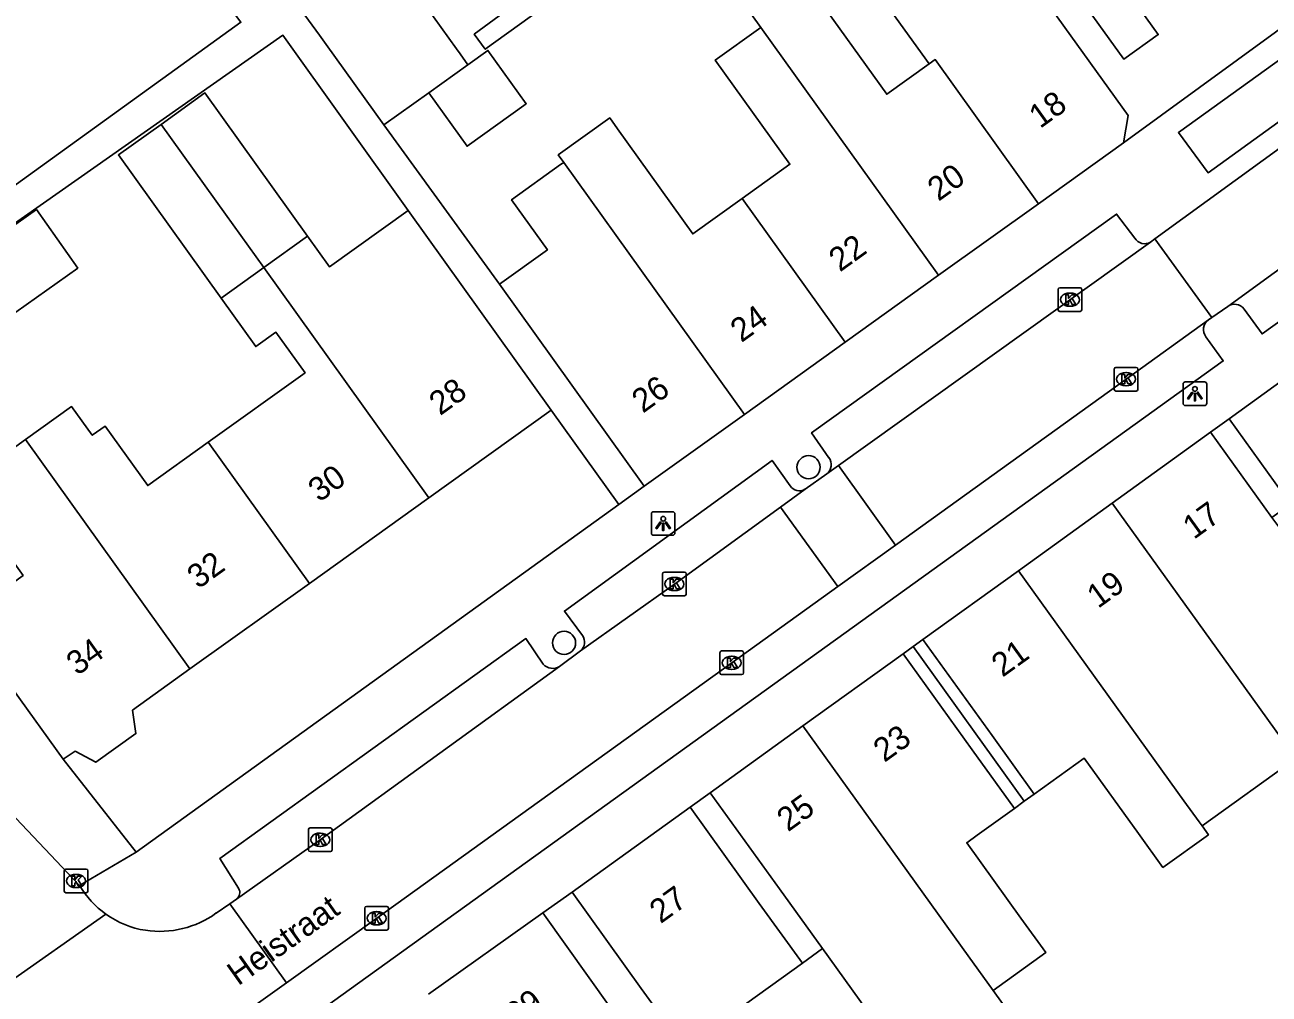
# Model space of a CAD drawing. Extents: x 161882 to 162509, y 381687 to 382379.
# Drawn here: x 162223.5 to 162276, y 381897.9 to 381938.8 of the extents above; entities that cross this region are included whole.
import ezdxf

# ---------------------------------------------------------------- set-up
doc = ezdxf.new("R2010")
doc.units = 0
for name, color, linetype in [('IMGEO_Boom', 7, 'Continuous'), ('IMGEO_Kolk', 7, 'Continuous'), ('IMGEO_Lichtpunt', 7, 'Continuous'), ('IMGEO_Openbare_ruimte_label', 7, 'Continuous'), ('IMGEO_Pand', 7, 'Continuous'), ('IMGEO_Pand_nummerreeks', 7, 'Continuous'), ('IMGEO_Pand_overbouw', 7, 'Continuous'), ('IMGEO_Rijbaan_lokaal_open', 7, 'Continuous'), ('IMGEO_Voetpad_open', 7, 'Continuous')]:
    doc.layers.add(name, color=color, linetype=linetype)

msp = doc.modelspace()

# ---------------------------------------------------------------- linework, layer by layer
at = {"layer": 'IMGEO_Boom'}
for centre in [(162256.59, 381920.171), (162246.271, 381912.756)]:
    msp.add_circle(centre, 0.489, dxfattribs=at)
at = {"layer": 'IMGEO_Kolk'}
for p, q in [((162267.12, 381926.817), (162267.12, 381927.669)), ((162267.195, 381927.743), (162268.047, 381927.743)), ((162267.608, 381927.523), (162267.633, 381927.523)), ((162268.121, 381927.669), (162268.121, 381926.817)), ((162267.631, 381926.963), (162267.606, 381926.963)), ((162268.047, 381926.743), (162267.195, 381926.743)), ((162269.563, 381924.384), (162270.415, 381924.384)), ((162269.488, 381923.458), (162269.488, 381924.31)), ((162269.976, 381924.164), (162270.001, 381924.164)), ((162270.489, 381924.31), (162270.489, 381923.458)), ((162270.415, 381923.384), (162269.563, 381923.384)), ((162269.999, 381923.604), (162269.974, 381923.604)), ((162250.428, 381914.817), (162250.428, 381915.669)), ((162250.503, 381915.743), (162251.355, 381915.743)), ((162250.916, 381915.523), (162250.941, 381915.523)), ((162251.429, 381915.669), (162251.429, 381914.817)), ((162250.939, 381914.963), (162250.914, 381914.963)), ((162251.355, 381914.743), (162250.503, 381914.743)), ((162252.846, 381911.491), (162252.846, 381912.343)), ((162252.921, 381912.417), (162253.773, 381912.417)), ((162253.847, 381912.343), (162253.847, 381911.491)), ((162253.334, 381912.197), (162253.359, 381912.197)), ((162253.773, 381911.417), (162252.921, 381911.417)), ((162253.357, 381911.637), (162253.332, 381911.637)), ((162235.558, 381904.95), (162236.41, 381904.95)), ((162235.483, 381904.024), (162235.483, 381904.876)), ((162235.971, 381904.73), (162235.996, 381904.73)), ((162236.484, 381904.876), (162236.484, 381904.024)), ((162236.41, 381903.95), (162235.558, 381903.95)), ((162235.994, 381904.17), (162235.969, 381904.17)), ((162225.176, 381902.283), (162225.176, 381903.135)), ((162225.251, 381903.209), (162226.103, 381903.209)), ((162225.664, 381902.989), (162225.689, 381902.989)), ((162226.177, 381903.135), (162226.177, 381902.283)), ((162225.687, 381902.429), (162225.662, 381902.429)), ((162226.103, 381902.209), (162225.251, 381902.209)), ((162237.861, 381900.708), (162237.861, 381901.56)), ((162237.936, 381901.634), (162238.788, 381901.634)), ((162238.349, 381901.414), (162238.374, 381901.414)), ((162238.862, 381901.56), (162238.862, 381900.708)), ((162238.372, 381900.854), (162238.347, 381900.854)), ((162238.788, 381900.634), (162237.936, 381900.634))]:
    msp.add_line(p, q, dxfattribs=at)
for points in [[(162267.12, 381926.817), (162267.12, 381927.669)], [(162267.195, 381927.743), (162268.047, 381927.743)], [(162268.121, 381927.669), (162268.121, 381926.817)], [(162267.441, 381927.443), (162267.564, 381927.443), (162267.564, 381927.292), (162267.694, 381927.443), (162267.858, 381927.443), (162267.712, 381927.292), (162267.865, 381927.043), (162267.713, 381927.043), (162267.628, 381927.207), (162267.564, 381927.14), (162267.564, 381927.043), (162267.441, 381927.043), (162267.441, 381927.443)], [(162268.047, 381926.743), (162267.195, 381926.743)], [(162269.563, 381924.384), (162270.415, 381924.384)], [(162269.488, 381923.458), (162269.488, 381924.31)], [(162269.809, 381924.084), (162269.932, 381924.084), (162269.932, 381923.933), (162270.062, 381924.084), (162270.226, 381924.084), (162270.08, 381923.933), (162270.233, 381923.684), (162270.081, 381923.684), (162269.996, 381923.848), (162269.932, 381923.781), (162269.932, 381923.684), (162269.809, 381923.684), (162269.809, 381924.084)], [(162270.489, 381924.31), (162270.489, 381923.458)], [(162270.415, 381923.384), (162269.563, 381923.384)], [(162250.428, 381914.817), (162250.428, 381915.669)], [(162250.503, 381915.743), (162251.355, 381915.743)], [(162250.749, 381915.443), (162250.872, 381915.443), (162250.872, 381915.292), (162251.002, 381915.443), (162251.166, 381915.443), (162251.02, 381915.292), (162251.173, 381915.043), (162251.021, 381915.043), (162250.936, 381915.207), (162250.872, 381915.14), (162250.872, 381915.043), (162250.749, 381915.043), (162250.749, 381915.443)], [(162251.429, 381915.669), (162251.429, 381914.817)], [(162251.355, 381914.743), (162250.503, 381914.743)], [(162252.846, 381911.491), (162252.846, 381912.343)], [(162252.921, 381912.417), (162253.773, 381912.417)], [(162253.847, 381912.343), (162253.847, 381911.491)], [(162253.167, 381912.117), (162253.29, 381912.117), (162253.29, 381911.966), (162253.42, 381912.117), (162253.584, 381912.117), (162253.438, 381911.966), (162253.591, 381911.717), (162253.439, 381911.717), (162253.354, 381911.881), (162253.29, 381911.814), (162253.29, 381911.717), (162253.167, 381911.717), (162253.167, 381912.117)], [(162253.773, 381911.417), (162252.921, 381911.417)], [(162235.558, 381904.95), (162236.41, 381904.95)], [(162235.483, 381904.024), (162235.483, 381904.876)], [(162235.804, 381904.65), (162235.927, 381904.65), (162235.927, 381904.499), (162236.057, 381904.65), (162236.221, 381904.65), (162236.075, 381904.499), (162236.228, 381904.25), (162236.076, 381904.25), (162235.991, 381904.414), (162235.927, 381904.347), (162235.927, 381904.25), (162235.804, 381904.25), (162235.804, 381904.65)], [(162236.484, 381904.876), (162236.484, 381904.024)], [(162236.41, 381903.95), (162235.558, 381903.95)], [(162225.176, 381902.283), (162225.176, 381903.135)], [(162225.251, 381903.209), (162226.103, 381903.209)], [(162225.497, 381902.909), (162225.62, 381902.909), (162225.62, 381902.758), (162225.75, 381902.909), (162225.914, 381902.909), (162225.768, 381902.758), (162225.921, 381902.509), (162225.769, 381902.509), (162225.684, 381902.673), (162225.62, 381902.606), (162225.62, 381902.509), (162225.497, 381902.509), (162225.497, 381902.909)], [(162226.177, 381903.135), (162226.177, 381902.283)], [(162226.103, 381902.209), (162225.251, 381902.209)], [(162237.861, 381900.708), (162237.861, 381901.56)], [(162237.936, 381901.634), (162238.788, 381901.634)], [(162238.182, 381901.334), (162238.305, 381901.334), (162238.305, 381901.183), (162238.435, 381901.334), (162238.599, 381901.334), (162238.453, 381901.183), (162238.606, 381900.934), (162238.454, 381900.934), (162238.369, 381901.098), (162238.305, 381901.031), (162238.305, 381900.934), (162238.182, 381900.934), (162238.182, 381901.334)], [(162238.862, 381901.56), (162238.862, 381900.708)], [(162238.788, 381900.634), (162237.936, 381900.634)]]:
    msp.add_lwpolyline(points, dxfattribs=at)
for centre, start, end in [((162267.197, 381927.667), 91.552, 178.448), ((162267.197, 381927.667), 91.552, 178.448), ((162268.045, 381927.667), 1.552, 88.448), ((162268.045, 381927.667), 1.552, 88.448), ((162267.197, 381926.819), 181.552, 268.448), ((162267.197, 381926.819), 181.552, 268.448), ((162268.045, 381926.819), 271.552, 358.448), ((162268.045, 381926.819), 271.552, 358.448), ((162269.565, 381924.308), 91.552, 178.448), ((162269.565, 381924.308), 91.552, 178.448), ((162270.413, 381924.308), 1.552, 88.448), ((162270.413, 381924.308), 1.552, 88.448), ((162269.565, 381923.46), 181.552, 268.448), ((162269.565, 381923.46), 181.552, 268.448), ((162270.413, 381923.46), 271.552, 358.448), ((162270.413, 381923.46), 271.552, 358.448), ((162250.505, 381915.667), 91.552, 178.448), ((162250.505, 381915.667), 91.552, 178.448), ((162251.353, 381915.667), 1.552, 88.448), ((162251.353, 381915.667), 1.552, 88.448), ((162250.505, 381914.819), 181.552, 268.448), ((162250.505, 381914.819), 181.552, 268.448), ((162251.353, 381914.819), 271.552, 358.448), ((162251.353, 381914.819), 271.552, 358.448), ((162252.923, 381912.341), 91.552, 178.448), ((162252.923, 381912.341), 91.552, 178.448), ((162253.771, 381912.341), 1.552, 88.448), ((162253.771, 381912.341), 1.552, 88.448), ((162252.923, 381911.493), 181.552, 268.448), ((162252.923, 381911.493), 181.552, 268.448), ((162253.771, 381911.493), 271.552, 358.448), ((162253.771, 381911.493), 271.552, 358.448), ((162235.56, 381904.874), 91.552, 178.448), ((162235.56, 381904.874), 91.552, 178.448), ((162236.408, 381904.874), 1.552, 88.448), ((162236.408, 381904.874), 1.552, 88.448), ((162235.56, 381904.026), 181.552, 268.448), ((162235.56, 381904.026), 181.552, 268.448), ((162236.408, 381904.026), 271.552, 358.448), ((162236.408, 381904.026), 271.552, 358.448), ((162225.253, 381903.133), 91.552, 178.448), ((162225.253, 381903.133), 91.552, 178.448), ((162226.101, 381903.133), 1.552, 88.448), ((162226.101, 381903.133), 1.552, 88.448), ((162225.253, 381902.285), 181.552, 268.448), ((162225.253, 381902.285), 181.552, 268.448), ((162226.101, 381902.285), 271.552, 358.448), ((162226.101, 381902.285), 271.552, 358.448), ((162237.938, 381901.558), 91.552, 178.448), ((162237.938, 381901.558), 91.552, 178.448), ((162238.786, 381901.558), 1.552, 88.448), ((162238.786, 381901.558), 1.552, 88.448), ((162237.938, 381900.71), 181.552, 268.448), ((162237.938, 381900.71), 181.552, 268.448), ((162238.786, 381900.71), 271.552, 358.448), ((162238.786, 381900.71), 271.552, 358.448)]:
    msp.add_arc(centre, 0.0765, start, end, dxfattribs=at)
for centre, major_axis, ratio, start_param, end_param in [((162267.607, 381927.243), (-0.387, 0.002), 0.722429, 4.712389, 7.853982), ((162267.632, 381927.243), (-0.39, 0.002), 0.717154, 1.570796, 4.712389), ((162269.975, 381923.884), (-0.387, 0.002), 0.722429, 4.712389, 7.853982), ((162270, 381923.884), (-0.39, 0.002), 0.717154, 1.570796, 4.712389), ((162250.915, 381915.243), (-0.387, 0.002), 0.722429, 4.712389, 7.853982), ((162250.94, 381915.243), (-0.39, 0.002), 0.717154, 1.570796, 4.712389), ((162253.333, 381911.917), (-0.387, 0.002), 0.722429, 4.712389, 7.853982), ((162253.358, 381911.917), (-0.39, 0.002), 0.717154, 1.570796, 4.712389), ((162235.97, 381904.45), (-0.387, 0.002), 0.722429, 4.712389, 7.853982), ((162235.995, 381904.45), (-0.39, 0.002), 0.717154, 1.570796, 4.712389), ((162225.663, 381902.709), (-0.387, 0.002), 0.722429, 4.712389, 7.853982), ((162225.688, 381902.709), (-0.39, 0.002), 0.717154, 1.570796, 4.712389), ((162238.348, 381901.134), (-0.387, 0.002), 0.722429, 4.712389, 7.853982), ((162238.373, 381901.134), (-0.39, 0.002), 0.717154, 1.570796, 4.712389)]:
    msp.add_ellipse(centre, major_axis=major_axis, ratio=ratio, start_param=start_param, end_param=end_param, dxfattribs=at)
at = {"layer": 'IMGEO_Lichtpunt'}
for p, q in [((162272.395, 381923.676), (162272.395, 381922.869)), ((162272.395, 381923.676), (162272.395, 381922.869)), ((162273.297, 381923.771), (162272.489, 381923.771)), ((162273.297, 381923.771), (162272.489, 381923.771)), ((162273.391, 381922.869), (162273.391, 381923.676)), ((162273.391, 381922.869), (162273.391, 381923.676)), ((162272.489, 381922.775), (162273.297, 381922.775)), ((162272.489, 381922.775), (162273.297, 381922.775)), ((162249.955, 381918.2), (162249.955, 381917.393)), ((162249.955, 381918.2), (162249.955, 381917.393)), ((162250.857, 381918.295), (162250.049, 381918.295)), ((162250.857, 381918.295), (162250.049, 381918.295)), ((162250.951, 381917.393), (162250.951, 381918.2)), ((162250.951, 381917.393), (162250.951, 381918.2)), ((162250.049, 381917.299), (162250.857, 381917.299)), ((162250.049, 381917.299), (162250.857, 381917.299))]:
    msp.add_line(p, q, dxfattribs=at)
for points in [[(162272.769, 381923.34), (162272.808, 381923.312), (162272.62, 381923.05), (162272.582, 381923.077), (162272.769, 381923.34)], [(162272.871, 381923.292), (162272.918, 381923.292), (162272.918, 381922.97), (162272.871, 381922.97), (162272.871, 381923.292)], [(162272.981, 381923.312), (162273.019, 381923.339), (162273.206, 381923.077), (162273.167, 381923.049), (162272.981, 381923.312)], [(162250.329, 381917.864), (162250.368, 381917.836), (162250.18, 381917.574), (162250.142, 381917.601), (162250.329, 381917.864)], [(162250.431, 381917.816), (162250.478, 381917.816), (162250.478, 381917.494), (162250.431, 381917.494), (162250.431, 381917.816)], [(162250.541, 381917.836), (162250.579, 381917.863), (162250.766, 381917.601), (162250.727, 381917.573), (162250.541, 381917.836)]]:
    msp.add_lwpolyline(points, dxfattribs=at)
for centre in [(162272.894, 381923.474), (162250.454, 381917.998)]:
    msp.add_circle(centre, 0.0994, dxfattribs=at)
for centre, start, end in [((162272.489, 381923.676), 90, 180), ((162272.489, 381923.676), 90, 180), ((162273.297, 381923.676), 0, 90), ((162273.297, 381923.676), 0, 90), ((162272.489, 381922.869), 180, 270), ((162272.489, 381922.869), 180, 270), ((162273.297, 381922.869), 270, 0), ((162273.297, 381922.869), 270, 360), ((162250.049, 381918.2), 90, 180), ((162250.049, 381918.2), 90, 180), ((162250.857, 381918.2), 0, 90), ((162250.857, 381918.2), 0, 90), ((162250.049, 381917.393), 180, 270), ((162250.049, 381917.393), 180, 270), ((162250.857, 381917.393), 270, 0), ((162250.857, 381917.393), 270, 360)]:
    msp.add_arc(centre, 0.0946, start, end, dxfattribs=at)
at = {"layer": 'IMGEO_Pand'}
for points in [[(162254.989, 381946.479), (162261.684, 381937.198)], [(162261.684, 381937.198), (162259.887, 381935.909), (162256.749, 381940.287), (162253.438, 381944.906), (162253.266, 381945.147), (162251.089, 381943.595)], [(162242.214, 381937.16), (162241.883, 381937.622), (162241.73, 381937.835), (162238.819, 381941.9)], [(162252.346, 381941.841), (162254.576, 381938.73)], [(162265.743, 381941.056), (162270.07, 381935.019), (162269.88, 381933.866)], [(162238.663, 381934.615), (162236.228, 381938.014), (162235.951, 381938.401), (162235.338, 381939.256)], [(162253.783, 381931.51), (162255.803, 381932.958), (162252.654, 381937.352), (162254.576, 381938.73)], [(162254.576, 381938.73), (162262.074, 381928.27)], [(162240.561, 381935.975), (162242.177, 381933.719), (162244.672, 381935.508), (162243.056, 381937.764), (162242.214, 381937.16)], [(162242.214, 381937.16), (162240.561, 381935.975)], [(162266.289, 381931.292), (162261.933, 381937.377), (162261.684, 381937.198)], [(162235.446, 381929.921), (162231.114, 381935.966), (162229.267, 381934.642)], [(162238.663, 381934.615), (162240.561, 381935.975)], [(162246.255, 381933.037), (162246.028, 381933.354), (162248.199, 381934.91), (162248.529, 381934.45), (162251.705, 381930.02), (162253.783, 381931.51)], [(162229.267, 381934.642), (162227.462, 381933.349), (162231.796, 381927.305)], [(162229.267, 381934.642), (162231.985, 381930.851), (162233.6, 381928.598)], [(162269.88, 381933.866), (162266.289, 381931.292)], [(162243.548, 381927.897), (162245.572, 381929.348), (162244.058, 381931.462), (162246.123, 381932.942), (162246.255, 381933.037)], [(162246.255, 381933.037), (162253.882, 381922.398)], [(162258.131, 381925.444), (162253.783, 381931.51)], [(162266.289, 381931.292), (162262.074, 381928.27)], [(162221.38, 381925.484), (162219.634, 381927.948), (162224.002, 381931.042), (162225.747, 381928.578), (162221.38, 381925.484)], [(162235.446, 381929.921), (162236.372, 381928.629), (162239.696, 381931.008)], [(162239.696, 381931.008), (162245.727, 381922.584)], [(162233.6, 381928.598), (162235.446, 381929.921)], [(162231.796, 381927.305), (162233.6, 381928.598)], [(162233.6, 381928.598), (162240.564, 381918.883)], [(162262.074, 381928.27), (162258.131, 381925.444)], [(162249.658, 381919.37), (162243.548, 381927.897)], [(162231.254, 381921.228), (162235.34, 381924.157), (162234.113, 381925.869), (162233.263, 381925.259), (162231.796, 381927.305)], [(162258.131, 381925.444), (162253.882, 381922.398)], [(162274.337, 381922.215), (162278.116, 381924.938)], [(162223.543, 381921.337), (162225.49, 381922.732), (162226.36, 381921.519), (162226.904, 381921.909), (162228.703, 381919.399), (162231.254, 381921.228)], [(162245.727, 381922.584), (162240.564, 381918.883)], [(162253.882, 381922.398), (162249.658, 381919.37)], [(162282.836, 381918.376), (162280.984, 381917.041), (162283.233, 381913.92), (162281.311, 381912.535), (162279.063, 381915.656), (162277.259, 381918.159), (162276.929, 381918.617), (162274.337, 381922.215)], [(162220.871, 381913.764), (162223.438, 381915.604), (162222.035, 381917.563), (162222.76, 381918.083), (162221.484, 381919.862), (162223.543, 381921.337)], [(162230.483, 381911.657), (162223.543, 381921.337)], [(162231.254, 381921.228), (162235.523, 381915.27)], [(162269.402, 381918.658), (162273.553, 381921.649)], [(162273.553, 381921.649), (162276.146, 381918.052), (162276.476, 381917.593), (162278.279, 381915.091), (162280.527, 381911.97), (162280.901, 381911.451), (162281.31, 381910.883), (162277.151, 381907.885)], [(162240.564, 381918.883), (162235.523, 381915.27)], [(162265.442, 381915.805), (162269.402, 381918.658)], [(162269.402, 381918.658), (162274.13, 381912.085), (162277.151, 381907.885)], [(162261.414, 381912.903), (162265.442, 381915.805)], [(162265.442, 381915.805), (162272.428, 381906.096), (162273.073, 381905.2), (162273.193, 381905.032)], [(162235.523, 381915.27), (162230.483, 381911.657)], [(162225.13, 381907.844), (162220.871, 381913.764)], [(162273.193, 381905.032), (162273.461, 381904.661), (162271.545, 381903.279), (162270.511, 381904.714), (162268.22, 381907.894), (162266.116, 381906.378), (162264.337, 381908.846), (162261.414, 381912.903)], [(162256.346, 381909.25), (162260.577, 381912.299)], [(162260.577, 381912.299), (162263.499, 381908.243), (162265.278, 381905.774), (162263.707, 381904.643), (162263.264, 381904.324), (162265.551, 381901.146), (162266.602, 381899.685), (162264.379, 381898.084)], [(162230.483, 381911.657), (162228.054, 381909.916), (162228.203, 381908.928), (162226.516, 381907.717), (162225.64, 381908.186), (162225.13, 381907.844)], [(162252.439, 381906.434), (162256.346, 381909.25)], [(162264.379, 381898.084), (162263.328, 381899.545), (162256.346, 381909.25)], [(162277.151, 381907.885), (162273.193, 381905.032)], [(162264.379, 381898.084), (162265.634, 381896.34), (162265.889, 381895.985), (162264.029, 381894.644), (162262.875, 381896.245), (162262.711, 381896.473), (162260.672, 381895.006), (162257.18, 381899.854), (162255.362, 381902.378), (162252.439, 381906.434)], [(162251.586, 381905.819), (162254.509, 381901.762), (162256.328, 381899.238), (162253.538, 381897.228), (162255.74, 381894.172), (162253.587, 381892.585), (162249.531, 381898.176), (162246.608, 381902.233)], [(162246.608, 381902.233), (162251.586, 381905.819)], [(162240.549, 381897.926), (162245.371, 381901.367)], [(162245.371, 381901.367), (162248.275, 381897.298), (162250.244, 381894.539), (162247.927, 381892.886), (162248.913, 381891.505), (162248.847, 381891.36), (162250.584, 381888.924), (162248.192, 381887.217)]]:
    msp.add_lwpolyline(points, dxfattribs=at)
at = {"layer": 'IMGEO_Pand_overbouw'}
for points in [[(162276.146, 381918.052), (162276.929, 381918.617), (162274.337, 381922.215), (162273.553, 381921.649)], [(162260.997, 381912.602), (162265.694, 381906.074), (162266.116, 381906.378), (162264.337, 381908.846), (162261.414, 381912.903)], [(162260.997, 381912.602), (162260.577, 381912.299), (162263.499, 381908.243), (162265.278, 381905.774), (162265.694, 381906.074)], [(162252.439, 381906.434), (162251.586, 381905.819), (162254.509, 381901.762), (162256.328, 381899.238), (162257.18, 381899.854), (162255.362, 381902.378)]]:
    msp.add_lwpolyline(points, close=True, dxfattribs=at)
at = {"layer": 'IMGEO_Rijbaan_lokaal_open'}
for points in [[(162243.291, 381975.571), (162250.83, 381966.065), (162257.599, 381957.53), (162265.697, 381946.277), (162271.344, 381938.429), (162269.9, 381937.391), (162264.255, 381945.235), (162256.181, 381956.455), (162249.437, 381964.96), (162241.902, 381974.46)], [(162269.88, 381933.866), (162279.505, 381940.876)], [(162279.329, 381936.842), (162273.449, 381932.601), (162272.199, 381934.296), (162278.121, 381938.561), (162279.329, 381936.842)], [(162271.201, 381929.808), (162282.553, 381938.052)], [(162283.901, 381933.941), (162274.276, 381926.959)], [(162257.85, 381920.248), (162271.019, 381929.676)], [(162271.019, 381929.676), (162271.201, 381929.808)], [(162271.201, 381929.808), (162273.607, 381926.495)], [(162274.276, 381926.959), (162273.607, 381926.495)], [(162273.607, 381926.495), (162273.463, 381926.395)], [(162273.463, 381926.395), (162269.991, 381923.887), (162260.256, 381916.887)], [(162257.355, 381919.894), (162257.85, 381920.248)], [(162260.256, 381916.887), (162257.85, 381920.248)], [(162256.439, 381919.238), (162257.355, 381919.894)], [(162255.399, 381918.484), (162256.439, 381919.238)], [(162246.97, 381912.418), (162250.926, 381915.24), (162255.399, 381918.484)], [(162257.825, 381915.139), (162255.399, 381918.484)], [(162260.256, 381916.887), (162257.825, 381915.139)], [(162257.825, 381915.139), (162253.349, 381911.92), (162238.365, 381901.138), (162234.555, 381898.412)], [(162246.083, 381911.765), (162246.97, 381912.418)], [(162232.444, 381901.94), (162235.981, 381904.447), (162246.083, 381911.765)], [(162221.938, 381906.686), (162222.15, 381906.388), (162225.828, 381902.52)], [(162232.166, 381901.749), (162232.444, 381901.94)], [(162226.939, 381901.305), (162222.611, 381898.266)], [(162231.596, 381901.357), (162232.166, 381901.749)], [(162234.555, 381898.412), (162232.166, 381901.749)], [(162234.555, 381898.412), (162224.359, 381891.116)]]:
    msp.add_lwpolyline(points, dxfattribs=at)
for centre, radius, start, end in [((162229.201, 381904.488), 3.905, 210.2704, 234.6094), ((162229.208, 381904.495), 3.915, 234.5843, 261.1747), ((162229.213, 381904.629), 4.047, 261.3847, 306.0645)]:
    msp.add_arc(centre, radius, start, end, dxfattribs=at)
at = {"layer": 'IMGEO_Voetpad_open'}
for points in [[(162248.956, 381943.21), (162242.479, 381938.444), (162242.946, 381937.81), (162254.989, 381946.479)], [(162229.626, 381942.938), (162232.631, 381938.95), (162219.25, 381929.308)], [(162219.1, 381927.669), (162234.406, 381938.399), (162239.696, 381931.008)], [(162243.548, 381927.897), (162238.663, 381934.615)], [(162284.992, 381932.454), (162275.73, 381925.794), (162274.968, 381926.846)], [(162257.444, 381920.574), (162256.715, 381921.627), (162269.59, 381930.858), (162270.357, 381929.842)], [(162273.358, 381925.677), (162274.088, 381924.659), (162225.354, 381889.595)], [(162245.727, 381922.584), (162248.583, 381918.595)], [(162274.337, 381922.215), (162273.553, 381921.649)], [(162247.044, 381913.072), (162246.287, 381914.102), (162255.052, 381920.457), (162255.814, 381919.389)], [(162248.583, 381918.595), (162249.658, 381919.37)], [(162248.583, 381918.595), (162228.211, 381903.922)], [(162232.539, 381902.399), (162231.748, 381903.664), (162244.66, 381912.939), (162245.394, 381911.86)], [(162261.414, 381912.903), (162260.997, 381912.602), (162260.577, 381912.299)], [(162225.13, 381907.844), (162228.211, 381903.922)], [(162252.439, 381906.434), (162251.586, 381905.819)], [(162228.211, 381903.922), (162225.828, 381902.52)], [(162246.608, 381902.233), (162245.371, 381901.367)]]:
    msp.add_lwpolyline(points, dxfattribs=at)
for centre, radius, start, end in [((162270.768, 381930.077), 0.473, 209.8014, 302.0447), ((162274.564, 381926.547), 0.503, 36.522, 124.9295), ((162273.767, 381925.984), 0.511, 126.4577, 216.9025), ((162257.065, 381920.278), 0.481, 307.0516, 38.0351), ((162256.206, 381919.643), 0.467, 212.9425, 299.8927), ((162246.646, 381912.786), 0.491, 311.4077, 35.6812), ((162245.794, 381912.214), 0.534, 221.5335, 302.7655), ((162232.242, 381902.221), 0.346, 305.6992, 30.9138)]:
    msp.add_arc(centre, radius, start, end, dxfattribs=at)

# ---------------------------------------------------------------- texts
at = {"layer": 'IMGEO_Openbare_ruimte_label'}
msp.add_text('Heistraat', height=1, rotation=35.3911, dxfattribs=at).set_placement((162232.519, 381898.261))
at = {"layer": 'IMGEO_Pand_nummerreeks'}
for s, rotation, p in [('18', 35.6322, (162266.357, 381934.441)), ('20', 35.6322, (162262.073, 381931.37)), ('22', 35.6346, (162257.911, 381928.386)), ('24', 35.6322, (162253.755, 381925.408)), ('28', 35.6329, (162241.04, 381922.325)), ('26', 35.6322, (162249.597, 381922.427)), ('30', 35.6329, (162235.938, 381918.668)), ('17', 35.7698, (162272.85, 381917.1)), ('32', 35.6322, (162230.832, 381915.007)), ('19', 35.7698, (162268.804, 381914.185)), ('34', 35.6322, (162225.732, 381911.352)), ('21', 35.7698, (162264.775, 381911.283)), ('23', 35.7812, (162259.79, 381907.689)), ('25', 35.7812, (162255.721, 381904.757)), ('27', 35.7678, (162250.344, 381900.882)), ('29', 35.5062, (162244.251, 381896.538))]:
    msp.add_text(s, height=1, rotation=rotation, dxfattribs=at).set_placement(p)

doc.saveas('drawing.dxf')
